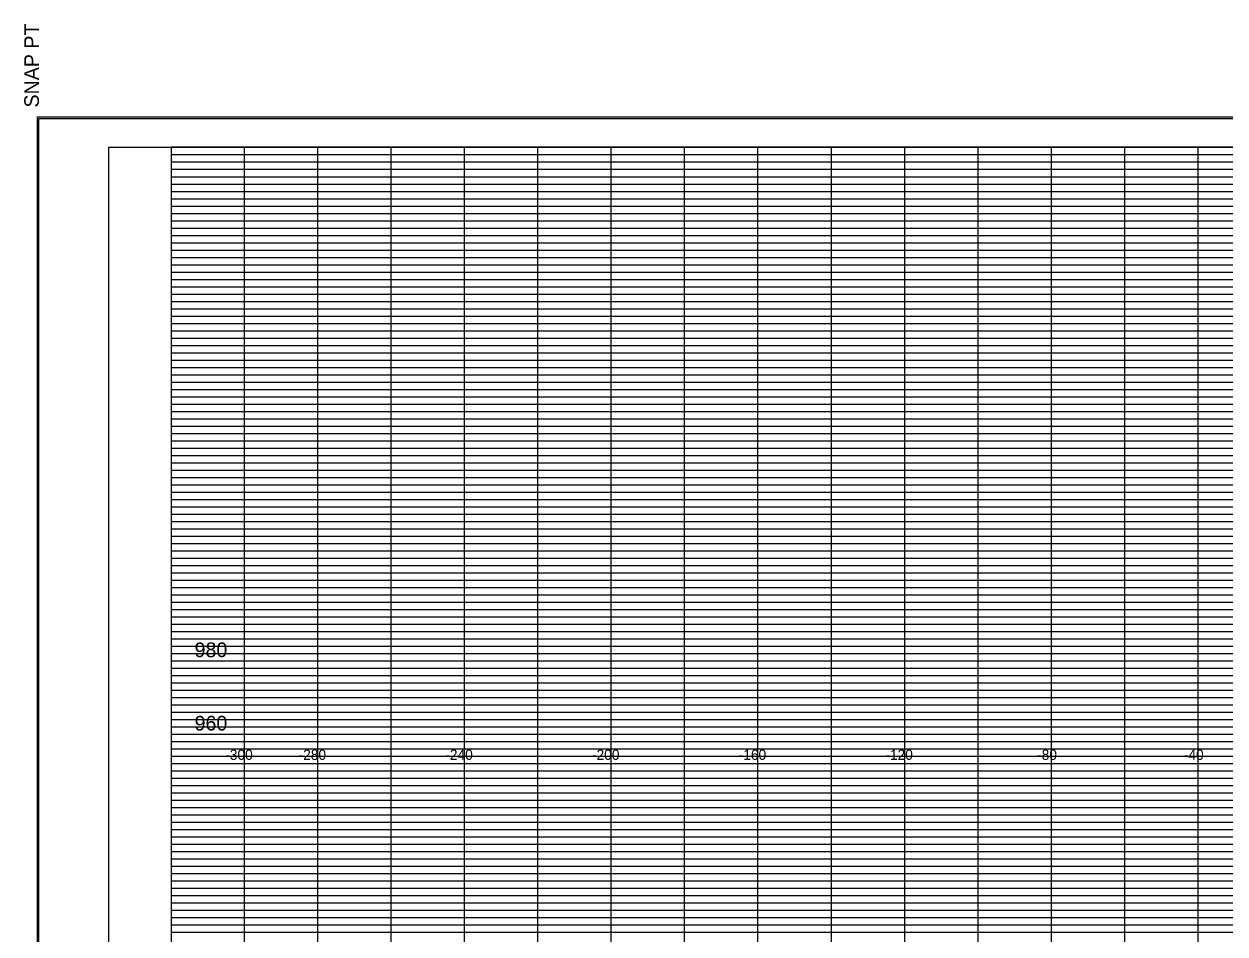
# Model space of a CAD drawing. Extents: x 2313580 to 2322968, y 282099 to 303247.
# Drawn here: x 2317632.4 to 2317959.8, y 287793.2 to 288041.3 of the extents above; entities that cross this region are included whole.
import ezdxf

# ---------------------------------------------------------------- set-up
doc = ezdxf.new("R2010")
doc.units = 0
for name, color, linetype in [('DESIGN - SHEET - Corner Text', 7, 'Continuous'), ('DESIGN - SHEET - Light Grid', 7, 'Continuous'), ('DESIGN - SHEET - Linework', 7, 'Continuous'), ('DESIGN - SHEET - Plot Shape', 7, 'Continuous'), ('DESIGN - TYPICAL - Text', 7, 'Continuous')]:
    doc.layers.add(name, color=color, linetype=linetype)

msp = doc.modelspace()

# ---------------------------------------------------------------- linework, layer by layer
at = {"layer": 'DESIGN - SHEET - Light Grid'}
for p, q in [((2317672.48, 288005.67), (2317832.48, 288005.67)), ((2317672.48, 288003.67), (2317832.48, 288003.67)), ((2317832.48, 288005.67), (2317992.48, 288005.67)), ((2317832.48, 288003.67), (2317992.48, 288003.67)), ((2317672.48, 288001.67), (2317832.48, 288001.67)), ((2317832.48, 288001.67), (2317992.48, 288001.67)), ((2317672.48, 287999.67), (2317832.48, 287999.67)), ((2317672.48, 287997.67), (2317832.48, 287997.67)), ((2317832.48, 287999.67), (2317992.48, 287999.67)), ((2317832.48, 287997.67), (2317992.48, 287997.67)), ((2317672.48, 287995.67), (2317832.48, 287995.67)), ((2317672.48, 287993.67), (2317832.48, 287993.67)), ((2317832.48, 287995.67), (2317992.48, 287995.67)), ((2317832.48, 287993.67), (2317992.48, 287993.67)), ((2317672.48, 287991.67), (2317832.48, 287991.67)), ((2317832.48, 287991.67), (2317992.48, 287991.67)), ((2317672.48, 287989.67), (2317832.48, 287989.67)), ((2317832.48, 287989.67), (2317992.48, 287989.67)), ((2317672.48, 287985.67), (2317832.48, 287985.67)), ((2317832.48, 287985.67), (2317992.48, 287985.67)), ((2317672.48, 287983.67), (2317832.48, 287983.67)), ((2317672.48, 287981.67), (2317832.48, 287981.67)), ((2317832.48, 287983.67), (2317992.48, 287983.67)), ((2317832.48, 287981.67), (2317992.48, 287981.67)), ((2317672.48, 287979.67), (2317832.48, 287979.67)), ((2317672.48, 287977.67), (2317832.48, 287977.67)), ((2317832.48, 287979.67), (2317992.48, 287979.67)), ((2317832.48, 287977.67), (2317992.48, 287977.67)), ((2317672.48, 287975.67), (2317832.48, 287975.67)), ((2317832.48, 287975.67), (2317992.48, 287975.67)), ((2317672.48, 287973.67), (2317832.48, 287973.67)), ((2317672.48, 287971.67), (2317832.48, 287971.67)), ((2317832.48, 287973.67), (2317992.48, 287973.67)), ((2317832.48, 287971.67), (2317992.48, 287971.67)), ((2317672.48, 287969.67), (2317832.48, 287969.67)), ((2317832.48, 287969.67), (2317992.48, 287969.67)), ((2317672.48, 287965.67), (2317832.48, 287965.67)), ((2317832.48, 287965.67), (2317992.48, 287965.67)), ((2317672.48, 287963.67), (2317832.48, 287963.67)), ((2317672.48, 287961.67), (2317832.48, 287961.67)), ((2317832.48, 287963.67), (2317992.48, 287963.67)), ((2317832.48, 287961.67), (2317992.48, 287961.67)), ((2317672.48, 287959.67), (2317832.48, 287959.67)), ((2317672.48, 287957.67), (2317832.48, 287957.67)), ((2317832.48, 287959.67), (2317992.48, 287959.67)), ((2317832.48, 287957.67), (2317992.48, 287957.67)), ((2317672.48, 287955.67), (2317832.48, 287955.67)), ((2317832.48, 287955.67), (2317992.48, 287955.67)), ((2317672.48, 287953.67), (2317832.48, 287953.67)), ((2317672.48, 287951.67), (2317832.48, 287951.67)), ((2317832.48, 287953.67), (2317992.48, 287953.67)), ((2317832.48, 287951.67), (2317992.48, 287951.67)), ((2317672.48, 287949.67), (2317832.48, 287949.67)), ((2317832.48, 287949.67), (2317992.48, 287949.67)), ((2317672.48, 287945.67), (2317832.48, 287945.67)), ((2317832.48, 287945.67), (2317992.48, 287945.67)), ((2317672.48, 287943.67), (2317832.48, 287943.67)), ((2317672.48, 287941.67), (2317832.48, 287941.67)), ((2317832.48, 287943.67), (2317992.48, 287943.67)), ((2317832.48, 287941.67), (2317992.48, 287941.67)), ((2317672.48, 287939.67), (2317832.48, 287939.67)), ((2317832.48, 287939.67), (2317992.48, 287939.67)), ((2317672.48, 287937.67), (2317832.48, 287937.67)), ((2317672.48, 287935.67), (2317832.48, 287935.67)), ((2317832.48, 287937.67), (2317992.48, 287937.67)), ((2317832.48, 287935.67), (2317992.48, 287935.67)), ((2317672.48, 287933.67), (2317832.48, 287933.67)), ((2317672.48, 287931.67), (2317832.48, 287931.67)), ((2317832.48, 287933.67), (2317992.48, 287933.67)), ((2317832.48, 287931.67), (2317992.48, 287931.67)), ((2317672.48, 287929.67), (2317832.48, 287929.67)), ((2317832.48, 287929.67), (2317992.48, 287929.67)), ((2317672.48, 287925.67), (2317832.48, 287925.67)), ((2317832.48, 287925.67), (2317992.48, 287925.67)), ((2317672.48, 287923.67), (2317832.48, 287923.67)), ((2317672.48, 287921.67), (2317832.48, 287921.67)), ((2317832.48, 287923.67), (2317992.48, 287923.67)), ((2317832.48, 287921.67), (2317992.48, 287921.67)), ((2317672.48, 287919.67), (2317832.48, 287919.67)), ((2317832.48, 287919.67), (2317992.48, 287919.67)), ((2317672.48, 287917.67), (2317832.48, 287917.67)), ((2317672.48, 287915.67), (2317832.48, 287915.67)), ((2317832.48, 287917.67), (2317992.48, 287917.67)), ((2317832.48, 287915.67), (2317992.48, 287915.67)), ((2317672.48, 287913.67), (2317832.48, 287913.67)), ((2317672.48, 287911.67), (2317832.48, 287911.67)), ((2317832.48, 287913.67), (2317992.48, 287913.67)), ((2317832.48, 287911.67), (2317992.48, 287911.67)), ((2317672.48, 287909.67), (2317832.48, 287909.67)), ((2317832.48, 287909.67), (2317992.48, 287909.67)), ((2317672.48, 287905.67), (2317832.48, 287905.67)), ((2317832.48, 287905.67), (2317992.48, 287905.67)), ((2317672.48, 287903.67), (2317832.48, 287903.67)), ((2317832.48, 287903.67), (2317992.48, 287903.67)), ((2317672.48, 287901.67), (2317832.48, 287901.67)), ((2317672.48, 287899.67), (2317832.48, 287899.67)), ((2317832.48, 287901.67), (2317992.48, 287901.67)), ((2317832.48, 287899.67), (2317992.48, 287899.67)), ((2317672.48, 287897.67), (2317832.48, 287897.67)), ((2317672.48, 287895.67), (2317832.48, 287895.67)), ((2317832.48, 287897.67), (2317992.48, 287897.67)), ((2317832.48, 287895.67), (2317992.48, 287895.67)), ((2317672.48, 287893.67), (2317832.48, 287893.67)), ((2317832.48, 287893.67), (2317992.48, 287893.67)), ((2317672.48, 287891.67), (2317832.48, 287891.67)), ((2317672.48, 287889.67), (2317832.48, 287889.67)), ((2317832.48, 287891.67), (2317992.48, 287891.67)), ((2317832.48, 287889.67), (2317992.48, 287889.67)), ((2317672.48, 287885.67), (2317832.48, 287885.67)), ((2317832.48, 287885.67), (2317992.48, 287885.67)), ((2317672.48, 287883.67), (2317832.48, 287883.67)), ((2317832.48, 287883.67), (2317992.48, 287883.67)), ((2317672.48, 287881.67), (2317832.48, 287881.67)), ((2317672.48, 287879.67), (2317832.48, 287879.67)), ((2317832.48, 287881.67), (2317992.48, 287881.67)), ((2317832.48, 287879.67), (2317992.48, 287879.67)), ((2317672.48, 287877.67), (2317832.48, 287877.67)), ((2317672.48, 287875.67), (2317832.48, 287875.67)), ((2317832.48, 287877.67), (2317992.48, 287877.67)), ((2317832.48, 287875.67), (2317992.48, 287875.67)), ((2317672.48, 287873.67), (2317832.48, 287873.67)), ((2317832.48, 287873.67), (2317992.48, 287873.67)), ((2317672.48, 287871.67), (2317832.48, 287871.67)), ((2317672.48, 287869.67), (2317832.48, 287869.67)), ((2317832.48, 287871.67), (2317992.48, 287871.67)), ((2317832.48, 287869.67), (2317992.48, 287869.67)), ((2317672.48, 287865.67), (2317832.48, 287865.67)), ((2317672.48, 287863.67), (2317832.48, 287863.67)), ((2317832.48, 287865.67), (2317992.48, 287865.67)), ((2317832.48, 287863.67), (2317992.48, 287863.67)), ((2317672.48, 287861.67), (2317832.48, 287861.67)), ((2317672.48, 287859.67), (2317832.48, 287859.67)), ((2317832.48, 287861.67), (2317992.48, 287861.67)), ((2317832.48, 287859.67), (2317992.48, 287859.67)), ((2317672.48, 287857.67), (2317832.48, 287857.67)), ((2317832.48, 287857.67), (2317992.48, 287857.67)), ((2317672.48, 287855.67), (2317832.48, 287855.67)), ((2317672.48, 287853.67), (2317832.48, 287853.67)), ((2317832.48, 287855.67), (2317992.48, 287855.67)), ((2317832.48, 287853.67), (2317992.48, 287853.67)), ((2317672.48, 287851.67), (2317832.48, 287851.67)), ((2317672.48, 287849.67), (2317832.48, 287849.67)), ((2317832.48, 287851.67), (2317992.48, 287851.67)), ((2317832.48, 287849.67), (2317992.48, 287849.67)), ((2317672.48, 287845.67), (2317832.48, 287845.67)), ((2317672.48, 287843.67), (2317832.48, 287843.67)), ((2317832.48, 287845.67), (2317992.48, 287845.67)), ((2317832.48, 287843.67), (2317992.48, 287843.67)), ((2317672.48, 287841.67), (2317832.48, 287841.67)), ((2317672.48, 287839.67), (2317832.48, 287839.67)), ((2317832.48, 287841.67), (2317992.48, 287841.67)), ((2317832.48, 287839.67), (2317992.48, 287839.67)), ((2317672.48, 287837.67), (2317832.48, 287837.67)), ((2317832.48, 287837.67), (2317992.48, 287837.67)), ((2317672.48, 287835.67), (2317832.48, 287835.67)), ((2317672.48, 287833.67), (2317832.48, 287833.67)), ((2317832.48, 287835.67), (2317992.48, 287835.67)), ((2317832.48, 287833.67), (2317992.48, 287833.67)), ((2317672.48, 287831.67), (2317832.48, 287831.67)), ((2317832.48, 287831.67), (2317992.48, 287831.67)), ((2317672.48, 287829.67), (2317832.48, 287829.67)), ((2317832.48, 287829.67), (2317992.48, 287829.67)), ((2317672.48, 287825.67), (2317832.48, 287825.67)), ((2317672.48, 287823.67), (2317832.48, 287823.67)), ((2317832.48, 287825.67), (2317992.48, 287825.67)), ((2317832.48, 287823.67), (2317992.48, 287823.67)), ((2317672.48, 287821.67), (2317832.48, 287821.67)), ((2317832.48, 287821.67), (2317992.48, 287821.67)), ((2317672.48, 287819.67), (2317832.48, 287819.67)), ((2317672.48, 287817.67), (2317832.48, 287817.67)), ((2317832.48, 287819.67), (2317992.48, 287819.67)), ((2317832.48, 287817.67), (2317992.48, 287817.67)), ((2317672.48, 287815.67), (2317832.48, 287815.67)), ((2317672.48, 287813.67), (2317832.48, 287813.67)), ((2317832.48, 287815.67), (2317992.48, 287815.67)), ((2317832.48, 287813.67), (2317992.48, 287813.67)), ((2317672.48, 287811.67), (2317832.48, 287811.67)), ((2317832.48, 287811.67), (2317992.48, 287811.67)), ((2317672.48, 287809.67), (2317832.48, 287809.67)), ((2317832.48, 287809.67), (2317992.48, 287809.67)), ((2317672.48, 287805.67), (2317832.48, 287805.67)), ((2317672.48, 287803.67), (2317832.48, 287803.67)), ((2317832.48, 287805.67), (2317992.48, 287805.67)), ((2317832.48, 287803.67), (2317992.48, 287803.67)), ((2317672.48, 287801.67), (2317832.48, 287801.67)), ((2317832.48, 287801.67), (2317992.48, 287801.67)), ((2317672.48, 287799.67), (2317832.48, 287799.67)), ((2317672.48, 287797.67), (2317832.48, 287797.67)), ((2317832.48, 287799.67), (2317992.48, 287799.67)), ((2317832.48, 287797.67), (2317992.48, 287797.67)), ((2317672.48, 287795.67), (2317832.48, 287795.67)), ((2317832.48, 287795.67), (2317992.48, 287795.67)), ((2317672.48, 287793.67), (2317832.48, 287793.67)), ((2317832.48, 287793.67), (2317992.48, 287793.67))]:
    msp.add_line(p, q, dxfattribs=at)
at = {"layer": 'DESIGN - SHEET - Linework'}
for p, q in [((2317636.02, 287579.39), (2317636.02, 288015.95)), ((2317636.02, 288015.95), (2318316.82, 288015.95)), ((2317692.48, 287587.67), (2317692.48, 288007.67)), ((2317712.48, 287587.67), (2317712.48, 288007.67)), ((2317732.48, 287587.67), (2317732.48, 288007.67)), ((2317752.48, 287587.67), (2317752.48, 288007.67)), ((2317772.48, 287587.67), (2317772.48, 288007.67)), ((2317792.48, 287587.67), (2317792.48, 288007.67)), ((2317812.48, 287587.67), (2317812.48, 288007.67)), ((2317832.48, 287587.67), (2317832.48, 288007.67)), ((2317852.48, 287587.67), (2317852.48, 288007.67)), ((2317872.48, 287587.67), (2317872.48, 288007.67)), ((2317892.48, 287587.67), (2317892.48, 288007.67)), ((2317912.48, 287587.67), (2317912.48, 288007.67)), ((2317932.48, 287587.67), (2317932.48, 288007.67)), ((2317952.48, 287587.67), (2317952.48, 288007.67)), ((2317672.48, 287987.67), (2318232.48, 287987.67)), ((2317672.48, 287967.67), (2318312.48, 287967.67)), ((2317672.48, 287947.67), (2318312.48, 287947.67)), ((2317672.48, 287927.67), (2318312.48, 287927.67)), ((2317672.48, 287907.67), (2318312.48, 287907.67)), ((2317672.48, 287887.67), (2318312.48, 287887.67)), ((2317672.48, 287867.67), (2318312.48, 287867.67)), ((2317672.48, 287847.67), (2318312.48, 287847.67)), ((2317672.48, 287827.67), (2318312.48, 287827.67)), ((2317672.48, 287807.67), (2318312.48, 287807.67))]:
    msp.add_line(p, q, dxfattribs=at)
msp.add_lwpolyline([(2317672.48, 288007.67), (2317672.48, 287587.67), (2318312.48, 287587.67), (2318312.48, 288007.67), (2317672.48, 288007.67)], dxfattribs=at)
at = {"layer": 'DESIGN - SHEET - Plot Shape'}
for points in [[(2317636.42, 288015.55), (2318316.42, 288015.55), (2318316.42, 287579.79), (2317636.42, 287579.79)], [(2317655.48, 288007.67), (2318312.48, 288007.67), (2318312.48, 287582.67), (2317655.48, 287582.67)]]:
    msp.add_lwpolyline(points, close=True, dxfattribs=at)

# ---------------------------------------------------------------- texts
at = {"layer": 'DESIGN - SHEET - Corner Text'}
msp.add_text('  SNAP PT', height=4, rotation=90, dxfattribs=at).set_placement((2317636.42, 288015.55))
at = {"layer": 'DESIGN - SHEET - Linework'}
msp.add_text('-', height=0.0001, dxfattribs=at).set_placement((2317692.48, 287847.67))
at = {"layer": 'DESIGN - TYPICAL - Text'}
for s, height, p in [('980', 4, (2317678.86, 287868.67)), ('960', 4, (2317678.86, 287848.67)), ('-300', 2.8, (2317687.22, 287840.67)), ('-280', 2.8, (2317707.22, 287840.67)), ('-240', 2.8, (2317747.22, 287840.67)), ('-200', 2.8, (2317787.22, 287840.67)), ('-160', 2.8, (2317827.22, 287840.67)), ('-120', 2.8, (2317867.22, 287840.67)), ('-80', 2.8, (2317908.59, 287840.67)), ('-40', 2.8, (2317948.59, 287840.67))]:
    msp.add_text(s, height=height, dxfattribs=at).set_placement(p)

doc.saveas('drawing.dxf')
